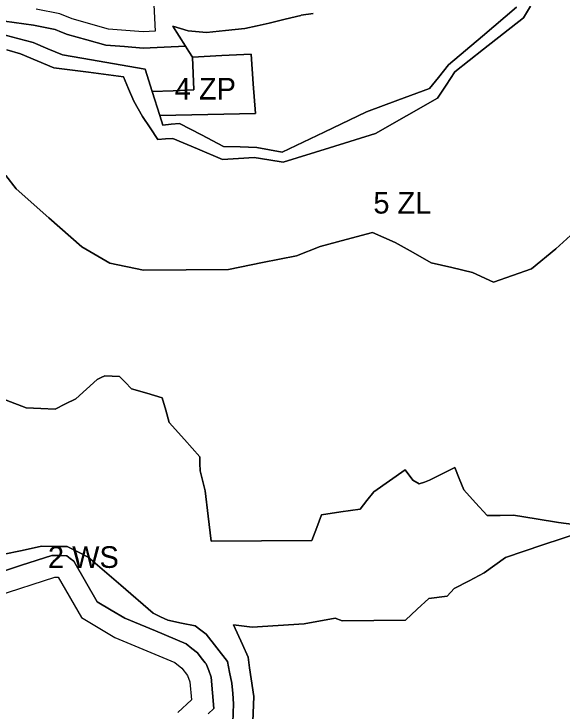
# Model space of a CAD drawing. Extents: x 7423691 to 7425475, y 5552085 to 5554331.
# Drawn here: x 7424587.5 to 7424789.8, y 5552663.9 to 5552921.5 of the extents above; entities that cross this region are included whole.
import ezdxf

# ---------------------------------------------------------------- set-up
doc = ezdxf.new("R2010")
doc.units = 0
for name, color, linetype in [('linia_zabudowy_nieprzekraczalna', 7, 'Continuous'), ('linie_rozgraniczajace', 7, 'Continuous'), ('oznaczenia_przeznaczen', 7, 'Continuous')]:
    doc.layers.add(name, color=color, linetype=linetype)

msp = doc.modelspace()

# ---------------------------------------------------------------- linework, layer by layer
at = {"layer": 'linia_zabudowy_nieprzekraczalna'}
for points in [[(7424639.14, 5552924.89), (7424639.61, 5552915.08), (7424635.25, 5552914.87), (7424622.44, 5552915.85), (7424608.95, 5552919.64), (7424604.41, 5552921.46), (7424595.75, 5552923.2)], [(7424559.55, 5552707.41), (7424569.21, 5552703.73), (7424581.21, 5552706.46), (7424602.66, 5552713.4), (7424603.78, 5552713.38), (7424612.4, 5552698.46), (7424624.81, 5552691.11), (7424646.93, 5552681.85), (7424649.5, 5552679.77), (7424651.53, 5552677.14), (7424652.42, 5552674.73), (7424652.99, 5552668.07), (7424648.05, 5552663.36)]]:
    msp.add_lwpolyline(points, dxfattribs=at)
at = {"layer": 'linie_rozgraniczajace'}
for points in [[(7424583.44, 5552913.81), (7424589, 5552912.34), (7424594.56, 5552910.87), (7424600.01, 5552908.62), (7424605.46, 5552906.36), (7424616.09, 5552904.51), (7424626.71, 5552902.66), (7424635.96, 5552901.04), (7424638.57, 5552892.79), (7424641.36, 5552883.96), (7424641.36, 5552883.96), (7424642.51, 5552880.34), (7424645.58, 5552880.69), (7424648.64, 5552881.04), (7424656.76, 5552876.79), (7424664.88, 5552872.53), (7424670.99, 5552872.34), (7424677.11, 5552872.14), (7424681.79, 5552871.29), (7424686.47, 5552870.45), (7424702.05, 5552877.85), (7424717.63, 5552885.26), (7424729.23, 5552889.57), (7424740.82, 5552893.88), (7424744.2, 5552897.97), (7424747.86, 5552902.61), (7424760.39, 5552913.3), (7424772.92, 5552923.98)], [(7424584.89, 5552908.19), (7424589.98, 5552906.68), (7424596.12, 5552904.13), (7424602.26, 5552901.58), (7424615.07, 5552899.93), (7424627.89, 5552898.28), (7424629.85, 5552893.76), (7424631.81, 5552889.23), (7424633.37, 5552886.43), (7424634.94, 5552883.63), (7424637.8, 5552879.35), (7424640.66, 5552875.06), (7424643.41, 5552875.27), (7424646.17, 5552875.48), (7424655.32, 5552871.58), (7424664.47, 5552867.69), (7424670.35, 5552868.09), (7424676.23, 5552868.49), (7424681.58, 5552867.6), (7424686.93, 5552866.71), (7424703.92, 5552872.01), (7424720.91, 5552877.31), (7424732.35, 5552883.8), (7424743.78, 5552890.3), (7424747, 5552895.2), (7424750.22, 5552900.1), (7424755.49, 5552904.25), (7424760.75, 5552908.4), (7424768.17, 5552914.2), (7424775.59, 5552920.01), (7424778.2, 5552924.32)], [(7424772.92, 5552923.98), (7424760.39, 5552913.3), (7424747.86, 5552902.61), (7424744.2, 5552897.97), (7424740.82, 5552893.88), (7424729.23, 5552889.57), (7424717.63, 5552885.26), (7424702.05, 5552877.85), (7424686.47, 5552870.45), (7424681.79, 5552871.29), (7424677.11, 5552872.14), (7424670.99, 5552872.34), (7424664.88, 5552872.53), (7424656.76, 5552876.79), (7424648.64, 5552881.04), (7424645.58, 5552880.69), (7424642.51, 5552880.34), (7424641.36, 5552883.96)], [(7424778.2, 5552924.32), (7424775.59, 5552920.01), (7424768.17, 5552914.2), (7424760.75, 5552908.4), (7424755.49, 5552904.25), (7424750.22, 5552900.1), (7424747, 5552895.2), (7424743.78, 5552890.3), (7424732.35, 5552883.8)], [(7424697.89, 5552921.64), (7424693.52, 5552920.96), (7424693.37, 5552920.93), (7424687.59, 5552919.5), (7424681.66, 5552918.05), (7424677.22, 5552917.04), (7424672.77, 5552916.03), (7424665.62, 5552915.32), (7424658.52, 5552914.61), (7424651.78, 5552915.26), (7424646.15, 5552916.94), (7424650.81, 5552909.62), (7424642.99, 5552909.24), (7424635.17, 5552908.86), (7424628.28, 5552909.39), (7424621.39, 5552909.91), (7424614.36, 5552911.89), (7424607.32, 5552913.86), (7424605.01, 5552914.78), (7424602.7, 5552915.69), (7424594.74, 5552917.28), (7424580.39, 5552919.29)], [(7424641.36, 5552883.96), (7424659.04, 5552884.34), (7424676.71, 5552884.72), (7424675.86, 5552895.69), (7424675.02, 5552906.65), (7424664.2, 5552906.07), (7424653.4, 5552905.48), (7424652.1, 5552907.55), (7424650.81, 5552909.62), (7424646.15, 5552916.94), (7424651.78, 5552915.26), (7424658.52, 5552914.61), (7424665.62, 5552915.32), (7424672.77, 5552916.03), (7424677.22, 5552917.04), (7424681.66, 5552918.05), (7424687.59, 5552919.5), (7424693.37, 5552920.93), (7424693.52, 5552920.96), (7424697.89, 5552921.64)], [(7424580.39, 5552919.29), (7424594.74, 5552917.28), (7424602.7, 5552915.69), (7424605.01, 5552914.78), (7424607.32, 5552913.86), (7424614.36, 5552911.89), (7424621.39, 5552909.91), (7424628.28, 5552909.39), (7424635.17, 5552908.86), (7424642.99, 5552909.24), (7424650.81, 5552909.62), (7424652.1, 5552907.55), (7424653.4, 5552905.48), (7424653.39, 5552905.48), (7424653.65, 5552899.45), (7424653.91, 5552893.42), (7424646.24, 5552893.11), (7424638.57, 5552892.79), (7424635.96, 5552901.04), (7424626.71, 5552902.66), (7424616.09, 5552904.51), (7424605.46, 5552906.36), (7424600.01, 5552908.62), (7424594.56, 5552910.87), (7424589, 5552912.34), (7424583.44, 5552913.81)], [(7424732.35, 5552883.8), (7424720.91, 5552877.31), (7424703.92, 5552872.01), (7424686.93, 5552866.71), (7424681.58, 5552867.6), (7424676.23, 5552868.49), (7424670.35, 5552868.09), (7424664.47, 5552867.69), (7424655.32, 5552871.58), (7424646.17, 5552875.48), (7424643.41, 5552875.27), (7424640.66, 5552875.06), (7424637.8, 5552879.35), (7424634.94, 5552883.63), (7424633.37, 5552886.43), (7424631.81, 5552889.23), (7424629.85, 5552893.76), (7424627.89, 5552898.28), (7424615.07, 5552899.93), (7424602.26, 5552901.58), (7424596.12, 5552904.13), (7424589.98, 5552906.68), (7424584.89, 5552908.19)], [(7424756.69, 5552826.01), (7424749.12, 5552827.78), (7424741.54, 5552829.55), (7424734.86, 5552833.28), (7424728.18, 5552837.02), (7424719.84, 5552840.75), (7424710.16, 5552838.15), (7424700.47, 5552835.56), (7424691.74, 5552832.12), (7424679.24, 5552829.59), (7424666.74, 5552827.05), (7424651.03, 5552826.93), (7424635.32, 5552826.81), (7424622.95, 5552829.38), (7424612.52, 5552835.48), (7424600.41, 5552846.14), (7424588.3, 5552856.8), (7424584.49, 5552861.75)], [(7424584.49, 5552861.75), (7424588.3, 5552856.8), (7424600.41, 5552846.14), (7424612.52, 5552835.48), (7424622.95, 5552829.38), (7424635.32, 5552826.81), (7424651.03, 5552826.93), (7424666.74, 5552827.05), (7424679.24, 5552829.59), (7424691.74, 5552832.12), (7424700.47, 5552835.56), (7424710.16, 5552838.15), (7424719.84, 5552840.75), (7424728.18, 5552837.02), (7424734.86, 5552833.28), (7424741.54, 5552829.55), (7424749.12, 5552827.78), (7424756.69, 5552826.01), (7424764.54, 5552822.36), (7424778.47, 5552827.26), (7424787.47, 5552834.64), (7424796.93, 5552843.32)], [(7424796.93, 5552843.32), (7424787.47, 5552834.64), (7424778.47, 5552827.26), (7424764.54, 5552822.36), (7424756.69, 5552826.01)], [(7424577.19, 5552781.58), (7424592.05, 5552775.93), (7424597.4, 5552775.71), (7424602.75, 5552775.49), (7424606.54, 5552777.4), (7424610.33, 5552779.31), (7424614.31, 5552782.88), (7424618.29, 5552786.46), (7424619.67, 5552787.11), (7424621.05, 5552787.77), (7424623.76, 5552787.66), (7424626.47, 5552787.54), (7424628.59, 5552785.42), (7424630.96, 5552783.03), (7424636.61, 5552781.32), (7424642.26, 5552779.61), (7424643.52, 5552775.11), (7424644.78, 5552770.6), (7424650.42, 5552764.22), (7424656.06, 5552757.85), (7424656.12, 5552755.35), (7424656.19, 5552752.64), (7424657.2, 5552748.77), (7424658.13, 5552745.26), (7424659.24, 5552735.96), (7424660.36, 5552726.66), (7424678.93, 5552726.81), (7424697.5, 5552726.95), (7424699.26, 5552731.72), (7424701.01, 5552736.49), (7424708.13, 5552737.51), (7424715.25, 5552738.53), (7424717.79, 5552741.75), (7424720.33, 5552744.97), (7424726.1, 5552748.99), (7424731.87, 5552753.01), (7424734.68, 5552749.22), (7424737.1, 5552747.85), (7424739, 5552748.56), (7424740.9, 5552749.27), (7424745.54, 5552751.62), (7424750.18, 5552753.96), (7424751.86, 5552749.8), (7424753.53, 5552745.64), (7424757.86, 5552740.89), (7424762.19, 5552736.13)], [(7424802.62, 5552731.75), (7424788.53, 5552733.56), (7424780.18, 5552734.91), (7424771.84, 5552736.25), (7424767.01, 5552736.19), (7424762.19, 5552736.13), (7424757.86, 5552740.89), (7424753.53, 5552745.64), (7424751.86, 5552749.8), (7424750.18, 5552753.96), (7424745.54, 5552751.62), (7424740.9, 5552749.27), (7424739, 5552748.56), (7424737.1, 5552747.85), (7424734.68, 5552749.22), (7424731.87, 5552753.01), (7424726.1, 5552748.99), (7424720.33, 5552744.97), (7424717.79, 5552741.75), (7424715.25, 5552738.53), (7424708.13, 5552737.51), (7424701.01, 5552736.49), (7424699.26, 5552731.72), (7424697.5, 5552726.95), (7424678.93, 5552726.81), (7424660.36, 5552726.66), (7424659.24, 5552735.96), (7424658.13, 5552745.26), (7424657.2, 5552748.77), (7424656.19, 5552752.64), (7424656.12, 5552755.35), (7424656.06, 5552757.85), (7424650.42, 5552764.22), (7424644.78, 5552770.6), (7424643.52, 5552775.11), (7424642.26, 5552779.61), (7424636.61, 5552781.32), (7424630.96, 5552783.03), (7424628.59, 5552785.42), (7424626.47, 5552787.54), (7424623.76, 5552787.66), (7424621.05, 5552787.77), (7424619.67, 5552787.11), (7424618.29, 5552786.46), (7424614.31, 5552782.88), (7424610.33, 5552779.31), (7424606.54, 5552777.4), (7424602.75, 5552775.49), (7424597.4, 5552775.71), (7424592.05, 5552775.93), (7424577.19, 5552781.58)], [(7424762.19, 5552736.13), (7424767.01, 5552736.19), (7424771.84, 5552736.25), (7424780.18, 5552734.91), (7424788.53, 5552733.56), (7424802.62, 5552731.75)], [(7424796.59, 5552729.96), (7424782.73, 5552725.32), (7424768.86, 5552720.68), (7424764.94, 5552717.83), (7424761.01, 5552714.97), (7424755.48, 5552712.1), (7424749.95, 5552709.23), (7424747.35, 5552706.43), (7424740.66, 5552705.52), (7424736.35, 5552701.55), (7424732.05, 5552697.57), (7424720.37, 5552697.45), (7424708.7, 5552697.32), (7424706.06, 5552698.27), (7424694.59, 5552696.2), (7424684.99, 5552695.57), (7424675.38, 5552694.95), (7424668.6, 5552695.74), (7424671.84, 5552688.48), (7424673.91, 5552683.84), (7424674.51, 5552679.87), (7424675.1, 5552675.9), (7424676.09, 5552669.35), (7424675.59, 5552656.96)], [(7424675.59, 5552656.96), (7424676.09, 5552669.35), (7424675.1, 5552675.9), (7424674.51, 5552679.87), (7424673.91, 5552683.84), (7424671.84, 5552688.48), (7424668.6, 5552695.74), (7424675.38, 5552694.95), (7424684.99, 5552695.57), (7424694.59, 5552696.2), (7424706.06, 5552698.27), (7424708.7, 5552697.32), (7424720.37, 5552697.45), (7424732.05, 5552697.57), (7424736.35, 5552701.55), (7424740.66, 5552705.52), (7424747.35, 5552706.43), (7424749.95, 5552709.23), (7424755.48, 5552712.1), (7424761.01, 5552714.97), (7424764.94, 5552717.83), (7424768.86, 5552720.68), (7424782.73, 5552725.32), (7424796.59, 5552729.96)], [(7424668.3, 5552659.76), (7424668.57, 5552666.64), (7424668.24, 5552670.43), (7424667.91, 5552674.22), (7424667.12, 5552678.26), (7424666.34, 5552682.3), (7424662.42, 5552687.3), (7424658.51, 5552692.3), (7424656.43, 5552693.85), (7424654.35, 5552695.41), (7424649.36, 5552696.44), (7424644.36, 5552697.47), (7424641.66, 5552698.76), (7424638.95, 5552700.06), (7424626.96, 5552710.45), (7424614.97, 5552720.83), (7424611.06, 5552722.79), (7424607.15, 5552724.74), (7424602.43, 5552724.77), (7424597.71, 5552724.81), (7424590.51, 5552723.27), (7424583.3, 5552721.73)], [(7424583.3, 5552721.73), (7424590.51, 5552723.27), (7424597.71, 5552724.81), (7424602.43, 5552724.77), (7424607.15, 5552724.74), (7424611.06, 5552722.79), (7424614.97, 5552720.83), (7424626.96, 5552710.45)], [(7424579.09, 5552714.18), (7424590.28, 5552717.8), (7424601.48, 5552721.43), (7424604.28, 5552721.37), (7424607.08, 5552721.31), (7424608.33, 5552720.32), (7424609.58, 5552719.33), (7424613.93, 5552711.8), (7424618.28, 5552704.27), (7424623.34, 5552701.27), (7424628.41, 5552698.27), (7424639.74, 5552693.53), (7424651.07, 5552688.79), (7424653.17, 5552687.1), (7424655.26, 5552685.4), (7424656.67, 5552683.57), (7424658.07, 5552681.75), (7424658.5, 5552681.35), (7424659.4, 5552678.92), (7424660.3, 5552676.5), (7424660.79, 5552670.72), (7424661.29, 5552664.94), (7424659.14, 5552662.89)], [(7424659.14, 5552662.89), (7424661.29, 5552664.94), (7424660.79, 5552670.72), (7424660.3, 5552676.5), (7424659.4, 5552678.92), (7424658.5, 5552681.35), (7424658.07, 5552681.75), (7424656.67, 5552683.57), (7424655.26, 5552685.4), (7424653.17, 5552687.1), (7424651.07, 5552688.79), (7424639.74, 5552693.53), (7424628.41, 5552698.27), (7424623.34, 5552701.27), (7424618.28, 5552704.27), (7424613.93, 5552711.8), (7424609.58, 5552719.33), (7424608.33, 5552720.32), (7424607.08, 5552721.31), (7424604.28, 5552721.37), (7424601.48, 5552721.43), (7424590.28, 5552717.8), (7424579.09, 5552714.18)], [(7424626.96, 5552710.45), (7424638.95, 5552700.06), (7424641.66, 5552698.76), (7424644.36, 5552697.47), (7424649.36, 5552696.44), (7424654.35, 5552695.41), (7424656.43, 5552693.85), (7424658.51, 5552692.3), (7424662.42, 5552687.3), (7424666.34, 5552682.3), (7424667.12, 5552678.26), (7424667.91, 5552674.22), (7424668.24, 5552670.43), (7424668.57, 5552666.64), (7424668.3, 5552659.76)]]:
    msp.add_lwpolyline(points, dxfattribs=at)
msp.add_lwpolyline([(7424638.57, 5552892.79), (7424646.24, 5552893.11), (7424653.91, 5552893.42), (7424653.65, 5552899.45), (7424653.39, 5552905.48), (7424653.4, 5552905.48), (7424664.2, 5552906.07), (7424675.02, 5552906.65), (7424675.86, 5552895.69), (7424676.71, 5552884.72), (7424659.04, 5552884.34), (7424641.36, 5552883.96), (7424641.36, 5552883.96)], close=True, dxfattribs=at)

# ---------------------------------------------------------------- texts
at = {"layer": 'oznaczenia_przeznaczen'}
for s, p in [('4 ZP', (7424646.86, 5552889.84)), ('5 ZL', (7424720.16, 5552847.72)), ('2 WS', (7424600.07, 5552716.83))]:
    msp.add_text(s, height=8, dxfattribs=at).set_placement(p)

doc.saveas('drawing.dxf')
